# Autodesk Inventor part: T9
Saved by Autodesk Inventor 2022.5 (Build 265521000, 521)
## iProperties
Created: 2024-07
Part Number: T9
Material: Generic
Document SubType Name: Modeling
Designer: AdminForWorker
Density: 1 g/cm^3
Appearance: Default
Title: T9
Author: AdminForWorker
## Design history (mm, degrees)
feature "T9"
body "Solid1"
